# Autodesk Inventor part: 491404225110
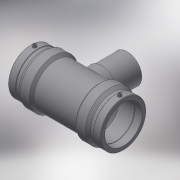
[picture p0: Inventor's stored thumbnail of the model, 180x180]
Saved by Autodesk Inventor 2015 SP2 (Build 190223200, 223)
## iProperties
Created: 2017-06
Part Number: 491404225110
Material: Generic
Description: PLASSON REDUCING TEE 225x110x225
Document SubType Name: Modeling
Designer: KIM
Mass: 11241.6 g
Surface Area: 8762.76 cm^2
Volume: 11241.6 cm^3
Density: 1 g/cm^3
Appearance: Default
Author: KIM
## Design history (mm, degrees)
derived "491404.ipt"
feature "Solid1::491404.ipt"
tag "TaggingFeature1"
body "Solid1"
other parameters: "d0" = 494, "d1" = 225, "d2" = 293, "d3" = 122, "d4" = 98.8, "d5" = 263.7, "d6" = 213.75, "d7" = 225, "d8" = 168 deg, "d10" = 48.8, "d11" = 16.26667, "d13" = 494, "d14" = 17.6296, "d17" = 202.5, "d18" = 225, "d19" = 3.52592, "d20" = 168 deg, "d22" = 272.49, "d23" = 293, "d25" = 135 deg, "d26" = 345.8, "d30" = 15, "d31" = 197.6, "d34" = 5 deg, "d35" = 15, "d39" = 5 deg, "d41" = 4, "d42" = 14, "d43" = 0, "d45" = 4, "d46" = 6, "d47" = 0, "d48" = -225, "d51" = 0, "d52" = 88, "d54" = 0, "d55" = 263.7, "d56" = 293, "d57" = 172.9, "d58" = 135 deg, "d59" = 122, "d60" = 122, "d61" = 135 deg, "d62" = 225, "d72" = 224.77, "d73" = 112.385, "d74" = -225, "d75" = 115.5, "d77" = 0, "d78" = 88, "d80" = 0, "d82" = 78.5, "d83" = 0, "d84" = 3, "d85" = 0, "d86" = 40.66667, "d87" = 267.0402, "d88" = 16.26667, "d89" = 3, "d90" = 0, "d_" = 225, "L_" = 494, "L_1" = 122, "D_" = 293, "d_2" = 12, "H_" = 225
